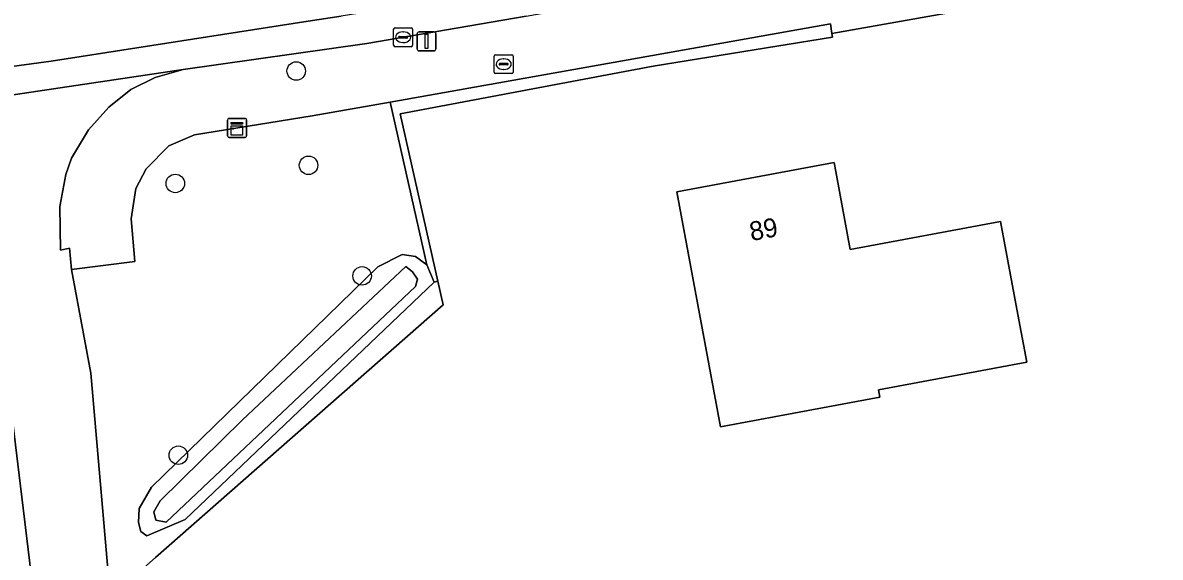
# Model space of a CAD drawing. Extents: x 157648 to 158502, y 379212 to 380938.
# Drawn here: x 158050.4 to 158110.5, y 380251.3 to 380279.5 of the extents above; entities that cross this region are included whole.
import ezdxf

# ---------------------------------------------------------------- set-up
doc = ezdxf.new("R2010")
doc.units = 0
for name, color, linetype in [('IMGEO_Boom', 7, 'Continuous'), ('IMGEO_Brandkraan', 7, 'Continuous'), ('IMGEO_Erf', 7, 'Continuous'), ('IMGEO_Grasland_overig', 7, 'Continuous'), ('IMGEO_Groenvoorziening', 7, 'Continuous'), ('IMGEO_Haag', 7, 'Continuous'), ('IMGEO_Hek', 7, 'Continuous'), ('IMGEO_Kast', 7, 'Continuous'), ('IMGEO_Kolk', 7, 'Continuous'), ('IMGEO_Lichtmast', 7, 'Continuous'), ('IMGEO_Pand', 7, 'Continuous'), ('IMGEO_Pand_nummerreeks', 7, 'Continuous'), ('IMGEO_Rijbaan_lokaal_gesloten', 7, 'Continuous'), ('IMGEO_Voetpad_open', 7, 'Continuous'), ('IMGEO_Waterloop', 7, 'Continuous')]:
    doc.layers.add(name, color=color, linetype=linetype)

msp = doc.modelspace()

# ---------------------------------------------------------------- linework, layer by layer
at = {"layer": 'IMGEO_Boom'}
for centre in [(158064.852, 380276.979), (158065.503, 380272), (158058.465, 380271.038), (158068.334, 380266.154), (158058.624, 380256.676)]:
    msp.add_circle(centre, 0.489, dxfattribs=at)
at = {"layer": 'IMGEO_Brandkraan'}
for p, q in [((158075.31, 380276.918), (158075.31, 380277.77)), ((158075.385, 380277.844), (158076.237, 380277.844)), ((158075.798, 380277.624), (158075.823, 380277.624)), ((158076.311, 380277.77), (158076.311, 380276.918)), ((158075.569, 380277.338), (158075.569, 380277.35)), ((158076.007, 380277.301), (158075.609, 380277.301)), ((158075.612, 380277.387), (158076.01, 380277.387)), ((158075.821, 380277.064), (158075.796, 380277.064)), ((158076.053, 380277.35), (158076.053, 380277.338)), ((158076.237, 380276.844), (158075.385, 380276.844))]:
    msp.add_line(p, q, dxfattribs=at)
for points in [[(158075.31, 380276.918), (158075.31, 380277.77)], [(158075.385, 380277.844), (158076.237, 380277.844)], [(158076.311, 380277.77), (158076.311, 380276.918)], [(158076.237, 380276.844), (158075.385, 380276.844)]]:
    msp.add_lwpolyline(points, dxfattribs=at)
for centre, radius, start, end in [((158075.387, 380277.768), 0.0765, 91.55205, 178.44795), ((158075.387, 380277.768), 0.0765, 91.55205, 178.44795), ((158076.235, 380277.768), 0.0765, 1.55205, 88.44795), ((158076.235, 380277.768), 0.0765, 1.55205, 88.44795), ((158075.609, 380277.347), 0.0403, 85.87752, 175.75265), ((158075.606, 380277.337), 0.0366, 178.93798, 274.71019), ((158076.01, 380277.344), 0.043, 264.86636, 352.45326), ((158076.014, 380277.349), 0.0386, 1.73085, 96.63898), ((158075.387, 380276.92), 0.0765, 181.55205, 268.44795), ((158075.387, 380276.92), 0.0765, 181.55205, 268.44795), ((158076.235, 380276.92), 0.0765, 271.55205, 358.44795), ((158076.235, 380276.92), 0.0765, 271.55205, 358.44795)]:
    msp.add_arc(centre, radius, start, end, dxfattribs=at)
for centre, major_axis, ratio, start_param, end_param in [((158075.797, 380277.344), (-0.387, 0.002), 0.722429, 4.712389, 7.853982), ((158075.822, 380277.344), (-0.39, 0.002), 0.717154, 1.570796, 4.712389)]:
    msp.add_ellipse(centre, major_axis=major_axis, ratio=ratio, start_param=start_param, end_param=end_param, dxfattribs=at)
at = {"layer": 'IMGEO_Erf'}
msp.add_lwpolyline([(158136.538, 380287.693), (158107.506, 380281.889), (158107.585, 380281.37), (158102.52, 380280.618), (158100.206, 380280.214), (158093.143, 380278.97), (158093.175, 380278.773), (158083.705, 380277.243), (158070.336, 380274.713), (158072.333, 380265.872), (158072.615, 380264.622), (158057.425, 380251.264), (158055.866, 380249.893), (158056.884, 380240.529), (158058.036, 380230.303), (158058.146, 380229.115), (158060.568, 380206.579), (158061.769, 380205.199), (158062.709, 380204.118), (158066.028, 380200.389)], dxfattribs=at)
msp.add_lwpolyline([(158092.185, 380259.088), (158087.269, 380258.17), (158084.95, 380270.591), (158093.263, 380272.144), (158094.12, 380267.553), (158102.061, 380269.036), (158102.979, 380264.121), (158103.45, 380261.597), (158095.615, 380260.134), (158095.688, 380259.742)], close=True, dxfattribs=at)
at = {"layer": 'IMGEO_Grasland_overig'}
msp.add_lwpolyline([(158069.794, 380093.44), (158064.454, 380132.929), (158062.905, 380144.992), (158061.172, 380159.684), (158059.333, 380173.963), (158056.338, 380200.176), (158053.424, 380227.702), (158050.772, 380251.122), (158049.888, 380258.392)], dxfattribs=at)
at = {"layer": 'IMGEO_Groenvoorziening'}
for points in [[(158093.143, 380278.97), (158093.078, 380279.48), (158069.812, 380275.337), (158071.747, 380266.746), (158072.138, 380265.828), (158072.333, 380265.872), (158070.336, 380274.713), (158083.705, 380277.243), (158093.175, 380278.773)], [(158071.747, 380266.746), (158071.158, 380267.178), (158070.456, 380267.292), (158069.165, 380266.627), (158057.206, 380254.99), (158056.56, 380253.859), (158056.521, 380253.123), (158056.653, 380252.652), (158056.958, 380252.409), (158058.987, 380253.281), (158072.138, 380265.828)], [(158057.978, 380253.146), (158057.441, 380253.25), (158057.329, 380253.685), (158057.669, 380254.27), (158062.023, 380258.545), (158070.64, 380266.651), (158071.002, 380266.374), (158071.258, 380265.982), (158071.148, 380265.592)]]:
    msp.add_lwpolyline(points, close=True, dxfattribs=at)
msp.add_lwpolyline([(158057.425, 380251.264), (158072.615, 380264.622), (158072.333, 380265.872), (158072.138, 380265.828), (158058.987, 380253.281), (158056.958, 380252.409), (158056.653, 380252.652), (158056.521, 380253.123), (158056.56, 380253.859), (158057.206, 380254.99), (158069.165, 380266.627), (158070.456, 380267.292), (158071.158, 380267.178), (158071.747, 380266.746), (158069.812, 380275.337), (158065.693, 380274.604), (158059.476, 380273.615), (158058.127, 380273.024), (158056.918, 380271.804), (158056.374, 380270.77), (158056.142, 380269.178), (158056.33, 380266.912), (158052.985, 380266.495), (158053.999, 380261.008), (158054.952, 380250.051)], dxfattribs=at)
at = {"layer": 'IMGEO_Haag'}
msp.add_lwpolyline([(158093.143, 380278.97), (158093.078, 380279.48), (158069.812, 380275.337), (158071.747, 380266.746), (158072.138, 380265.828), (158072.333, 380265.872), (158070.336, 380274.713), (158083.705, 380277.243), (158093.175, 380278.773)], close=True, dxfattribs=at)
at = {"layer": 'IMGEO_Hek'}
msp.add_lwpolyline([(158072.615, 380264.622), (158057.425, 380251.264), (158055.866, 380249.893), (158056.884, 380240.529), (158058.036, 380230.303), (158058.146, 380229.115), (158060.568, 380206.579), (158061.769, 380205.199), (158062.709, 380204.118), (158066.028, 380200.389), (158066.048, 380200.368), (158067.767, 380198.505), (158069.655, 380196.459), (158077.65, 380187.538), (158086.54, 380177.821), (158093, 380170.705), (158096.56, 380166.973)], dxfattribs=at)
at = {"layer": 'IMGEO_Kast'}
for p, q in [((158061.228, 380273.548), (158061.228, 380274.389)), ((158061.228, 380274.389), (158061.228, 380273.548)), ((158061.303, 380274.473), (158062.144, 380274.473)), ((158062.144, 380274.473), (158061.303, 380274.473)), ((158062.228, 380274.398), (158062.228, 380273.557)), ((158062.228, 380273.557), (158062.228, 380274.398)), ((158062.153, 380273.473), (158061.312, 380273.473)), ((158061.312, 380273.473), (158062.153, 380273.473))]:
    msp.add_line(p, q, dxfattribs=at)
for points in [[(158061.423, 380274.263), (158062.023, 380274.263), (158062.023, 380274.178), (158061.423, 380274.178), (158061.423, 380274.263)], [(158061.423, 380274.088), (158062.023, 380274.088), (158062.023, 380273.599), (158061.423, 380273.599), (158061.423, 380274.088)]]:
    msp.add_lwpolyline(points, dxfattribs=at)
msp.add_circle((158061.507, 380273.937), 0.0377, dxfattribs=at)
for centre, start, end in [((158061.306, 380274.395), 92.4484, 184.28452), ((158061.306, 380274.395), 92.4484, 184.28452), ((158062.15, 380274.395), 2.4484, 94.28452), ((158062.15, 380274.395), 2.4484, 94.28452), ((158061.306, 380273.551), 182.4484, 274.28452), ((158061.306, 380273.551), 182.4484, 274.28452), ((158062.15, 380273.551), 272.4484, 4.28452), ((158062.15, 380273.551), 272.4484, 4.28452)]:
    msp.add_arc(centre, 0.0779, start, end, dxfattribs=at)
at = {"layer": 'IMGEO_Kolk'}
for p, q in [((158069.999, 380278.341), (158069.999, 380279.193)), ((158070.074, 380279.267), (158070.926, 380279.267)), ((158070.301, 380278.81), (158070.699, 380278.81)), ((158070.487, 380279.047), (158070.512, 380279.047)), ((158071, 380279.193), (158071, 380278.341)), ((158070.926, 380278.267), (158070.074, 380278.267)), ((158070.258, 380278.761), (158070.258, 380278.773)), ((158070.696, 380278.724), (158070.298, 380278.724)), ((158070.51, 380278.487), (158070.485, 380278.487)), ((158070.742, 380278.773), (158070.742, 380278.761))]:
    msp.add_line(p, q, dxfattribs=at)
for points in [[(158069.999, 380278.341), (158069.999, 380279.193)], [(158070.074, 380279.267), (158070.926, 380279.267)], [(158071, 380279.193), (158071, 380278.341)], [(158070.926, 380278.267), (158070.074, 380278.267)]]:
    msp.add_lwpolyline(points, dxfattribs=at)
for centre, radius, start, end in [((158070.076, 380279.191), 0.0765, 91.55205, 178.44795), ((158070.076, 380279.191), 0.0765, 91.55205, 178.44795), ((158070.298, 380278.77), 0.0403, 85.87752, 175.75265), ((158070.703, 380278.772), 0.0386, 1.73085, 96.63898), ((158070.924, 380279.191), 0.0765, 1.55205, 88.44795), ((158070.924, 380279.191), 0.0765, 1.55205, 88.44795), ((158070.076, 380278.343), 0.0765, 181.55205, 268.44795), ((158070.076, 380278.343), 0.0765, 181.55205, 268.44795), ((158070.295, 380278.76), 0.0366, 178.93798, 274.71019), ((158070.699, 380278.767), 0.043, 264.86636, 352.45326), ((158070.924, 380278.343), 0.0765, 271.55205, 358.44795), ((158070.924, 380278.343), 0.0765, 271.55205, 358.44795)]:
    msp.add_arc(centre, radius, start, end, dxfattribs=at)
for centre, major_axis, ratio, start_param, end_param in [((158070.486, 380278.767), (-0.387, 0.002), 0.722429, 4.712389, 7.853982), ((158070.511, 380278.767), (-0.39, 0.002), 0.717154, 1.570796, 4.712389)]:
    msp.add_ellipse(centre, major_axis=major_axis, ratio=ratio, start_param=start_param, end_param=end_param, dxfattribs=at)
at = {"layer": 'IMGEO_Lichtmast'}
for p, q in [((158071.24, 380278.145), (158071.24, 380278.945)), ((158071.24, 380278.945), (158071.24, 380278.145)), ((158071.34, 380279.045), (158072.13, 380279.045)), ((158072.13, 380279.045), (158071.34, 380279.045)), ((158072.23, 380278.945), (158072.23, 380278.145)), ((158072.23, 380278.145), (158072.23, 380278.945)), ((158072.13, 380278.045), (158071.34, 380278.045)), ((158071.34, 380278.045), (158072.13, 380278.045))]:
    msp.add_line(p, q, dxfattribs=at)
msp.add_lwpolyline([(158071.66, 380278.92), (158071.81, 380278.92), (158071.81, 380278.17), (158071.66, 380278.17), (158071.66, 380278.92)], dxfattribs=at)
for centre, start, end in [((158071.34, 380278.945), 90, 180), ((158071.34, 380278.945), 90, 180), ((158072.13, 380278.945), 0, 90), ((158072.13, 380278.945), 360, 90), ((158071.34, 380278.145), 180, 270), ((158071.34, 380278.145), 180, 270), ((158072.13, 380278.145), 270, 0), ((158072.13, 380278.145), 270, 0)]:
    msp.add_arc(centre, 0.1, start, end, dxfattribs=at)
at = {"layer": 'IMGEO_Pand'}
msp.add_lwpolyline([(158092.185, 380259.088), (158095.688, 380259.742), (158095.615, 380260.134), (158103.45, 380261.597), (158102.979, 380264.121), (158102.061, 380269.036), (158094.12, 380267.553), (158093.263, 380272.144), (158084.95, 380270.591), (158087.269, 380258.17)], close=True, dxfattribs=at)
at = {"layer": 'IMGEO_Rijbaan_lokaal_gesloten'}
for points in [[(158039.85, 380274.219), (158058.874, 380277.06), (158068.585, 380278.44), (158077.006, 380279.879), (158089.567, 380282.141), (158093.444, 380282.893), (158099.311, 380284.03), (158101.619, 380284.478), (158116.541, 380287.303), (158129.533, 380289.899), (158133.995, 380290.767), (158133.722, 380292.14), (158116.281, 380288.679), (158093.196, 380284.325), (158075.248, 380281.174), (158067.228, 380279.885), (158065.478, 380279.614), (158051.914, 380277.506), (158039.275, 380275.799)], [(158039.275, 380275.799), (158051.914, 380277.506), (158065.478, 380279.614), (158067.228, 380279.885)], [(158065.822, 380156.025), (158061.718, 380190.062), (158061.111, 380195.192), (158060.555, 380200.03), (158060.056, 380204.365), (158059.926, 380205.548), (158057.35, 380229.035), (158057.218, 380230.232), (158056.125, 380240.2), (158054.952, 380250.051), (158053.999, 380261.008), (158052.985, 380266.495), (158052.883, 380267.616), (158052.406, 380267.511), (158052.367, 380269.826), (158052.678, 380271.514), (158052.989, 380272.367), (158053.873, 380273.874), (158054.947, 380275.069), (158056.119, 380276.011), (158057.395, 380276.638), (158058.874, 380277.06), (158039.85, 380274.219)], [(158049.888, 380258.392), (158050.772, 380251.122), (158053.424, 380227.702), (158056.338, 380200.176), (158059.333, 380173.963), (158061.172, 380159.684), (158062.905, 380144.992), (158064.454, 380132.929), (158069.794, 380093.44)]]:
    msp.add_lwpolyline(points, dxfattribs=at)
at = {"layer": 'IMGEO_Voetpad_open'}
msp.add_lwpolyline([(158077.006, 380279.879), (158068.585, 380278.44), (158058.874, 380277.06), (158057.395, 380276.638), (158056.119, 380276.011), (158054.947, 380275.069), (158053.873, 380273.874), (158052.989, 380272.367), (158052.678, 380271.514), (158052.367, 380269.826), (158052.406, 380267.511), (158052.883, 380267.616), (158052.985, 380266.495), (158056.33, 380266.912), (158056.142, 380269.178), (158056.374, 380270.77), (158056.918, 380271.804), (158058.127, 380273.024), (158059.476, 380273.615), (158065.693, 380274.604), (158069.812, 380275.337), (158093.078, 380279.48), (158093.143, 380278.97), (158100.206, 380280.214)], dxfattribs=at)
at = {"layer": 'IMGEO_Waterloop'}
msp.add_lwpolyline([(158071.148, 380265.592), (158071.258, 380265.982), (158071.002, 380266.374), (158070.64, 380266.651), (158062.023, 380258.545), (158057.669, 380254.27), (158057.329, 380253.685), (158057.441, 380253.25), (158057.978, 380253.146)], close=True, dxfattribs=at)

# ---------------------------------------------------------------- texts
at = {"layer": 'IMGEO_Pand_nummerreeks'}
msp.add_text('89', height=1, rotation=10.58178, dxfattribs=at).set_placement((158088.896, 380267.992))

doc.saveas('drawing.dxf')
